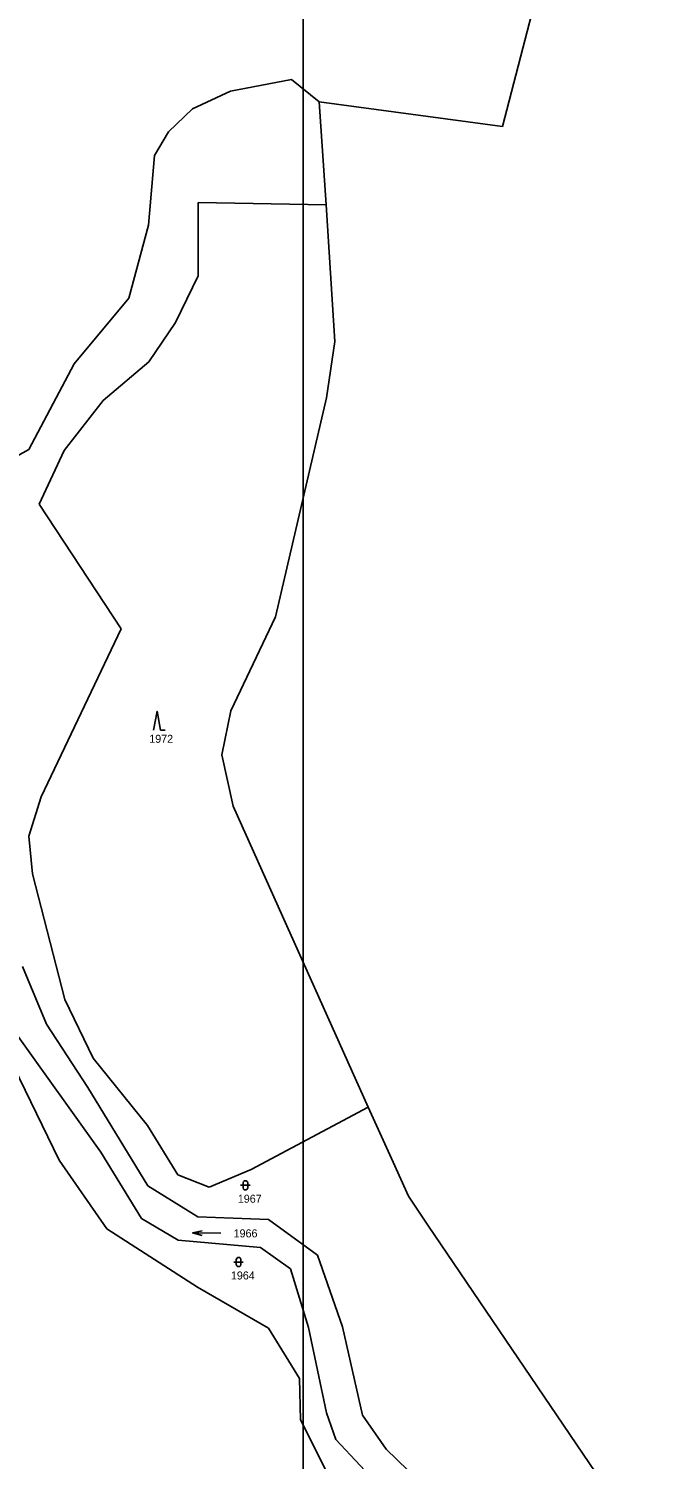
# Model space of a CAD drawing. Extents: x -802857 to -799647, y -1020285 to -1015884.
# Drawn here: x -801308.3 to -801173.6, y -1016866.1 to -1016562.1 of the extents above; entities that cross this region are included whole.
import ezdxf

# ---------------------------------------------------------------- set-up
doc = ezdxf.new("R2010")
doc.units = 0
for name, color, linetype in [('Default', 7, 'Continuous'), ('KLADY_ZMVM', 7, 'Continuous'), ('KN_HRANICE', 7, 'Continuous'), ('KN_KULTURY', 7, 'Continuous'), ('KN_PARCELY', 7, 'Continuous')]:
    doc.layers.add(name, color=color, linetype=linetype)

# ---------------------------------------------------------------- blocks, each defined once
blk = doc.blocks.new('308')
at = {"layer": 'Default'}
blk.add_lwpolyline([(-0.75, 0), (0, 4), (0.75, 0), (1.75, 0)], dxfattribs=at)
blk = doc.blocks.new('316')
at = {"layer": 'Default'}
for points in [[(-1, 1), (0.27, 1), (1, 1)], [(-0.5, 1.5), (-0.4, 1.79), (-0.15, 1.97), (0.16, 1.97), (0.41, 1.79), (0.51, 1.5), (0.51, 0.5), (0.41, 0.21), (0.16, 0.03), (-0.15, 0.03), (-0.4, 0.21), (-0.5, 0.5), (-0.5, 1.5)]]:
    blk.add_lwpolyline(points, dxfattribs=at)
blk = doc.blocks.new('802')
at = {"layer": 'Default'}
blk.add_line((-3, 0), (3, 0), dxfattribs=at)
blk.add_lwpolyline([(1, 0.5), (3, 0), (1, -0.5)], dxfattribs=at)

msp = doc.modelspace()

# ---------------------------------------------------------------- linework, layer by layer
at = {"layer": 'KLADY_ZMVM'}
msp.add_line((-801250, -1017000), (-801250, -1016500), dxfattribs=at)
at = {"layer": 'KN_HRANICE'}
for p, q in [((-801196.12, -1016537.94), (-801207.69, -1016582.91)), ((-801265.48, -1016575.38), (-801252.47, -1016572.88)), ((-801252.47, -1016572.88), (-801246.59, -1016577.62)), ((-801273.5, -1016579.11), (-801265.48, -1016575.38)), ((-801278.62, -1016584.04), (-801273.5, -1016579.11)), ((-801246.59, -1016577.62), (-801245.16, -1016599.53)), ((-801207.69, -1016582.91), (-801246.59, -1016577.62)), ((-801281.61, -1016589.02), (-801278.62, -1016584.04)), ((-801282.88, -1016603.88), (-801281.61, -1016589.02)), ((-801245.16, -1016599.53), (-801272.31, -1016599.02)), ((-801272.31, -1016599.02), (-801272.29, -1016614.6)), ((-801245.16, -1016599.53), (-801243.27, -1016628.57)), ((-801287.04, -1016619.33), (-801282.88, -1016603.88)), ((-801272.29, -1016614.6), (-801277.12, -1016624.55)), ((-801298.6, -1016633.32), (-801287.04, -1016619.33)), ((-801277.12, -1016624.55), (-801282.8, -1016632.88)), ((-801243.27, -1016628.57), (-801245.06, -1016640.51)), ((-801308.25, -1016651.49), (-801298.6, -1016633.32)), ((-801282.8, -1016632.88), (-801292.46, -1016641.08)), ((-801255.91, -1016687.07), (-801245.06, -1016640.51)), ((-801292.46, -1016641.08), (-801300.77, -1016651.72)), ((-801323.26, -1016659.76), (-801308.25, -1016651.49)), ((-801300.77, -1016651.72), (-801306.09, -1016663.1)), ((-801306.09, -1016663.1), (-801288.67, -1016689.61)), ((-801255.91, -1016687.07), (-801265.38, -1016707.01)), ((-801288.67, -1016689.61), (-801305.61, -1016725.29)), ((-801265.38, -1016707.01), (-801267.26, -1016716.41)), ((-801267.26, -1016716.41), (-801264.86, -1016727.26)), ((-801305.61, -1016725.29), (-801308.25, -1016733.62)), ((-801264.86, -1016727.26), (-801236.19, -1016791.22)), ((-801308.25, -1016733.62), (-801307.47, -1016741.69)), ((-801307.47, -1016741.69), (-801300.62, -1016768.35)), ((-801304.52, -1016773.59), (-801309.57, -1016761.31)), ((-801300.62, -1016768.35), (-801294.6, -1016780.8)), ((-801295.75, -1016787.05), (-801304.52, -1016773.59)), ((-801292.99, -1016800.81), (-801310.89, -1016775.73)), ((-801313.82, -1016777.7), (-801301.84, -1016802.52)), ((-801294.6, -1016780.8), (-801283.09, -1016795.11)), ((-801282.99, -1016807.91), (-801295.75, -1016787.05)), ((-801236.19, -1016791.22), (-801261.04, -1016804.5)), ((-801236.19, -1016791.22), (-801230.93, -1016802.94)), ((-801283.09, -1016795.11), (-801276.64, -1016805.63)), ((-801284.31, -1016814.88), (-801292.99, -1016800.81)), ((-801301.84, -1016802.52), (-801291.71, -1016817.07)), ((-801270, -1016808.23), (-801261.04, -1016804.5)), ((-801230.93, -1016802.94), (-801227.69, -1016810.17)), ((-801276.64, -1016805.63), (-801270, -1016808.23)), ((-801272.38, -1016814.51), (-801282.99, -1016807.91)), ((-801227.69, -1016810.17), (-801223.54, -1016816.29)), ((-801276.59, -1016819.48), (-801284.31, -1016814.88)), ((-801257.35, -1016815.11), (-801272.38, -1016814.51)), ((-801246.96, -1016822.66), (-801257.35, -1016815.11)), ((-801223.54, -1016816.29), (-801173.56, -1016890)), ((-801291.71, -1016817.07), (-801272.46, -1016829.44)), ((-801259.11, -1016821.03), (-801276.59, -1016819.48)), ((-801252.7, -1016825.56), (-801259.11, -1016821.03)), ((-801241.66, -1016837.9), (-801246.96, -1016822.66)), ((-801248.92, -1016838.05), (-801252.7, -1016825.56)), ((-801272.46, -1016829.44), (-801257.35, -1016838.15)), ((-801257.35, -1016838.15), (-801250.82, -1016848.86)), ((-801245.06, -1016856.14), (-801248.92, -1016838.05)), ((-801237.39, -1016856.65), (-801241.66, -1016837.9)), ((-801250.82, -1016848.86), (-801250.6, -1016857.65)), ((-801243.11, -1016861.82), (-801245.06, -1016856.14)), ((-801250.6, -1016857.65), (-801243.71, -1016871.35)), ((-801232.37, -1016863.85), (-801237.39, -1016856.65)), ((-801230.06, -1016875.69), (-801243.11, -1016861.82)), ((-801222, -1016873.95), (-801232.37, -1016863.85))]:
    msp.add_line(p, q, dxfattribs=at)

# ---------------------------------------------------------------- block references
at = {"layer": 'KN_KULTURY'}
for name, p in [('308', (-801281.03, -1016711.12)), ('316', (-801262.29, -1016808.83)), ('316', (-801263.73, -1016825.13))]:
    msp.add_blockref(name, p, dxfattribs=at)
at = {"layer": 'KN_KULTURY', "rotation": 179.221198}
msp.add_blockref('802', (-801270.48, -1016817.99), dxfattribs=at)

# ---------------------------------------------------------------- texts
at = {"layer": 'KN_PARCELY'}
for s, p in [('1972', (-801282.69, -1016713.82)), ('1967', (-801263.89, -1016811.53)), ('1966', (-801264.78, -1016818.89)), ('1964', (-801265.36, -1016827.83))]:
    msp.add_text(s, height=1.7, dxfattribs=at).set_placement(p)

doc.saveas('drawing.dxf')
